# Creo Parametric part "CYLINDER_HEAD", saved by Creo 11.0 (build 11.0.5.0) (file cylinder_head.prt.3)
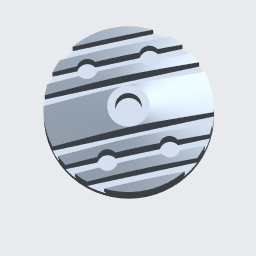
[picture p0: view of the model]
Materials in the file: 10038_S235JR

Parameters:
  MATERIAL = "10038_S235JR"
  PTC_MATERIAL_NAME = "10038_S235JR"
  PTC_MASTER_MATERIAL = "10038_S235JR"
  SELECT_EN_NAME = "S235JR"
  SELECT_DIN_NAME = "RSt37-2"
  SELECT_MATERIAL_NUMBER = "1.0038"
  SELECT_ASTM_NAME = "A 283 M Grade 2"
  MATERIAL_GROUP = "ME_ST_Baustahl"
  STANDARD_EN_DELIVERYSPEC = "DIN EN 10025-2"
  STANDARD_DIN_DELIVERYSPEC = "DIN EN 10025-2"

Other parameters: GEWICHT

Created from: STARTTEIL.PRT

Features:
  1. datum plane "RIGHT"
  2. datum plane "TOP"
  3. datum plane "FRONT"
  4. coordinate system
  5. datum axis
  6. datum axis
  7. datum axis
  8. revolve "Revolve 1"
  9. pattern "Pattern 1"
  10. extruded cut "Extrude 1"
  11. extruded cut "Extrude 1 [2]"
  12. extruded cut "Extrude 1 [3]"
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
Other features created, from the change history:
  extrusion "Extrude 1"
  mirror "Mirror 1"
  pattern "Pattern 1 (2)"
  extruded cut "Extrude 1 (2) [1]"
  extruded cut "Extrude 1 (2) [2]"
  extruded cut "Extrude 1 (2) [3]"
  mirror "Mirror 2"
  pattern "Pattern 1 (3)"
  extruded cut "Extrude 1 (3) [1]"
  extruded cut "Extrude 1 (3) [2]"
  extruded cut "Extrude 1 (3) [3]"
  mirror "Mirror 3"
  pattern "Pattern 1 (4)"
  extruded cut "Extrude 1 (4) [1]"
  extruded cut "Extrude 1 (4) [2]"
  extruded cut "Extrude 1 (4) [3]"
  extruded cut "Extrude 2"
  extruded cut "Extrude 3"
  mirror "Mirror 4"
  extruded cut "Extrude 3 (2)"
  mirror "Mirror 5"
  extruded cut "Extrude 3 (3)"
  mirror "Mirror 6"
  extruded cut "Extrude 3 (4)"

Other named items: A_Y, A_X, A_Z, CS0

Layers: BEZUGSACHSEN

Surfaces: 21 plane, 7 cylinder, 2 cone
